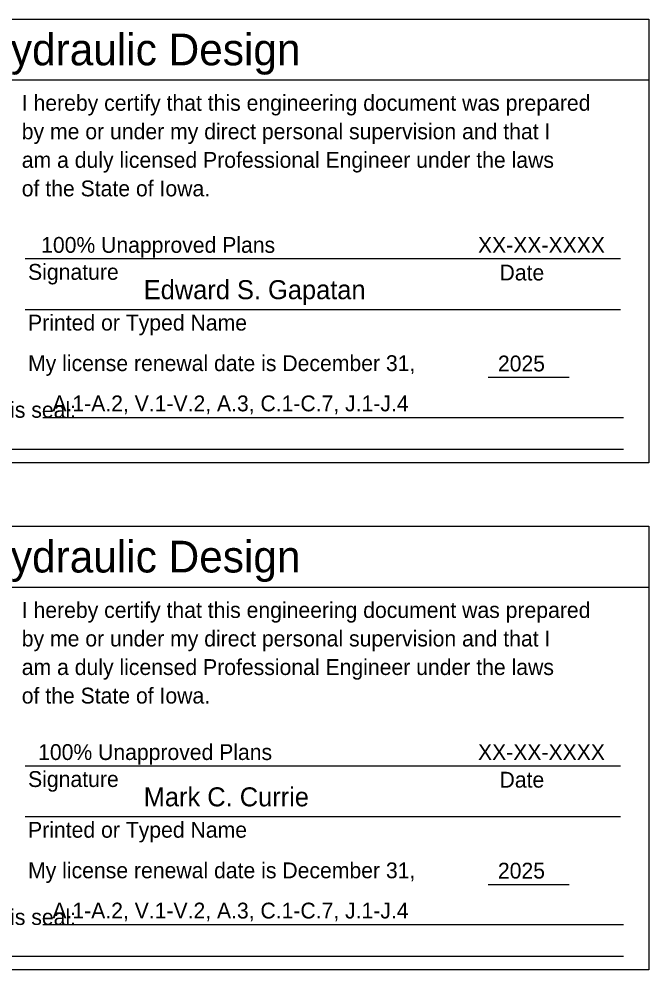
# Model space of a CAD drawing. Extents: x -0.84 to 4.97, y -1.01 to 2.42.
# Drawn here: x 4.551 to 4.966, y -0.986 to -0.361 of the extents above; entities that cross this region are included whole.
import ezdxf

# ---------------------------------------------------------------- set-up
doc = ezdxf.new("R2010")
doc.units = 0
for name, color, linetype in [('SheetGridMajor', 7, 'Continuous'), ('SheetGridMinor', 7, 'Continuous'), ('SheetText', 7, 'Continuous')]:
    doc.layers.add(name, color=color, linetype=linetype)

msp = doc.modelspace()

# ---------------------------------------------------------------- linework, layer by layer
at = {"layer": 'SheetGridMajor'}
for p, q in [((4.3407, -0.40149), (4.9657, -0.40149)), ((4.3407, -0.73482), (4.9657, -0.73482))]:
    msp.add_line(p, q, dxfattribs=at)
for points in [[(4.3407, -0.36149), (4.9657, -0.36149), (4.9657, -0.65315), (4.3407, -0.65315)], [(4.3407, -0.69482), (4.9657, -0.69482), (4.9657, -0.98649), (4.3407, -0.98649)]]:
    msp.add_lwpolyline(points, close=True, dxfattribs=at)
at = {"layer": 'SheetGridMinor'}
for p, q in [((4.94705, -0.51918), (4.55538, -0.51918)), ((4.94705, -0.55251), (4.55538, -0.55251)), ((4.91316, -0.59711), (4.85999, -0.59711)), ((4.56702, -0.62335), (4.94904, -0.62335)), ((4.56702, -0.62335), (4.94904, -0.62335)), ((4.35742, -0.64418), (4.94904, -0.64418)), ((4.94705, -0.85251), (4.55538, -0.85251)), ((4.94705, -0.88585), (4.55538, -0.88585)), ((4.91316, -0.93045), (4.85999, -0.93045)), ((4.56702, -0.95668), (4.94904, -0.95668)), ((4.56702, -0.95668), (4.94904, -0.95668)), ((4.35742, -0.97751), (4.94904, -0.97751))]:
    msp.add_line(p, q, dxfattribs=at)

# ---------------------------------------------------------------- texts
at = {"layer": 'SheetText'}
for s, height, p in [('Hydraulic Design', 0.0208333, (4.52596, -0.3919)), ('I hereby certify that this engineering document was prepared', 0.0104167, (4.55322, -0.42179)), ('by me or under my direct personal supervision and that I', 0.0104167, (4.55322, -0.44054)), ('am a duly licensed Professional Engineer under the laws', 0.0104167, (4.55322, -0.45929)), ('of the State of Iowa.', 0.0104167, (4.55322, -0.47804)), ('100% Unapproved Plans', 0.0104, (4.56599, -0.51515)), ('XX-XX-XXXX', 0.0104, (4.85326, -0.51515)), ('Signature', 0.010417, (4.55737, -0.53289)), ('Date', 0.010417, (4.86741, -0.53331)), ('Edward S. Gapatan', 0.0125, (4.63344, -0.54562)), ('Printed or Typed Name', 0.0104167, (4.55737, -0.56623)), ('My license renewal date is December 31,', 0.0104167, (4.55737, -0.59289)), ('2025', 0.0104, (4.86636, -0.59309)), ('A.1-A.2, V.1-V.2, A.3, C.1-C.7, J.1-J.4', 0.0104, (4.57339, -0.61932)), ('Pages or sheets covered by this seal:', 0.0104167, (4.35742, -0.62355)), ('Hydraulic Design', 0.0208333, (4.52596, -0.72524)), ('I hereby certify that this engineering document was prepared', 0.0104167, (4.55322, -0.75512)), ('by me or under my direct personal supervision and that I', 0.0104167, (4.55322, -0.77387)), ('am a duly licensed Professional Engineer under the laws', 0.0104167, (4.55322, -0.79262)), ('of the State of Iowa.', 0.0104167, (4.55322, -0.81137)), ('100% Unapproved Plans', 0.0104, (4.564, -0.84849)), ('XX-XX-XXXX', 0.0104, (4.85326, -0.84849)), ('Signature', 0.010417, (4.55737, -0.86623)), ('Date', 0.010417, (4.86741, -0.86665)), ('Mark C. Currie', 0.0125, (4.63344, -0.87895)), ('Printed or Typed Name', 0.0104167, (4.55737, -0.89956)), ('My license renewal date is December 31,', 0.0104167, (4.55737, -0.92623)), ('2025', 0.0104, (4.86636, -0.92642)), ('A.1-A.2, V.1-V.2, A.3, C.1-C.7, J.1-J.4', 0.0104, (4.57339, -0.95265)), ('Pages or sheets covered by this seal:', 0.0104167, (4.35742, -0.95689))]:
    msp.add_text(s, height=height, dxfattribs=at).set_placement(p)

doc.saveas('drawing.dxf')
